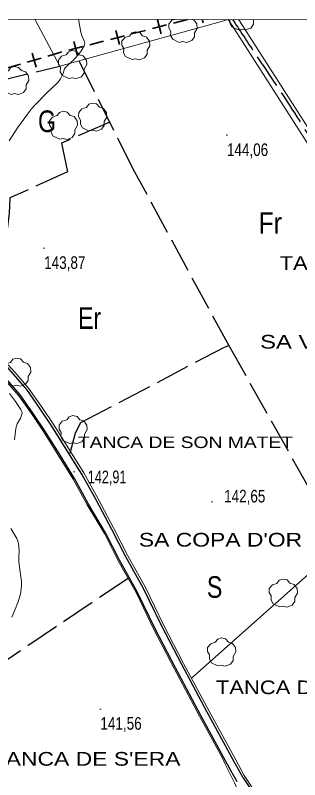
# Model space of a CAD drawing. Extents: x -807245 to 6129983, y -54972206 to 262146364.
# Drawn here: x 488544 to 488741, y 4383600 to 4384130 of the extents above; entities that cross this region are included whole.
import ezdxf
from ezdxf.enums import TextEntityAlignment as Align

# ---------------------------------------------------------------- set-up
doc = ezdxf.new("R2010")
doc.units = 0
doc.header["$LTSCALE"] = 4
doc.linetypes.add('LONG_DASHED', pattern=[7.5, 6, -1.5])
for name, color, linetype, lineweight in [('1', 7, 'Continuous', 13), ('25', 7, 'LONG_DASHED', 25), ('27', 7, 'Continuous', 25), ('29', 7, 'Continuous', 13), ('34', 7, 'Continuous', 35), ('36', 7, 'Continuous', 25), ('38', 7, 'Continuous', 25), ('51', 7, 'Continuous', 13), ('7', 7, 'Continuous', 13), ('9', 7, 'Continuous', 13)]:
    doc.layers.add(name, color=color, linetype=linetype, lineweight=lineweight)
doc.layers.add('31', color=7, linetype='Continuous')
doc.layers.add('5', color=7, linetype='Continuous')

msp = doc.modelspace()

# ---------------------------------------------------------------- linework, layer by layer
at = {"layer": '1'}
msp.add_lwpolyline([(487678, 4384129), (491255.4, 4384123.8), (491252.6, 4381811.5), (487674.1, 4381816.7)], close=True, dxfattribs=at)
at = {"layer": '25'}
for points in [[(488372.88, 4384127.06), (488373.97, 4384123.12), (488396.06, 4384079.88), (488412.22, 4384055.84), (488574.56, 4384095.18)], [(488692.19, 4383900.49), (488625.51, 4384023.7), (488587.87, 4384098.85)], [(488609.18, 4384056.33), (488575.68, 4384041.67), (488579.8, 4384021.67), (488539.84, 4384003.67), (488539.27, 4383993.1), (488537.77, 4383979.91), (488536.19, 4383973.03), (488532.76, 4383968.71), (488528.9, 4383965.38), (488486.3, 4383945.97)], [(488581.61, 4383826.5), (488585.47, 4383840.65), (488589.08, 4383847.74), (488688.78, 4383900.02), (488691.79, 4383901.19), (488769.37, 4383763.08)], [(488621.9, 4383739.52), (488493.76, 4383653.17), (488510.87, 4383620.49), (488455.31, 4383582.13)]]:
    msp.add_lwpolyline(points, dxfattribs=at)
at = {"layer": '27'}
msp.add_spline([(491255.21, 4383970.03), (491244.34, 4383967.52), (491230.36, 4383957.66), (491230.81, 4383957.81), (491230.81, 4383957.81), (491220.15, 4383951.47), (491212.7, 4383943.01), (491205.06, 4383944.23), (491184.85, 4383957.71), (491152.82, 4383981.27), (491128.36, 4384004.58), (491128.29, 4384004.88), (491122.26, 4384021.39), (491095.75, 4384034.59), (491071.07, 4384059.32), (491064.71, 4384065.12)], degree=3, dxfattribs=at)
at = {"layer": '29'}
for p, q in [((488666.31, 4384127.56), (488666.32, 4384127.56)), ((488666.32, 4384127.56), (488666.33, 4384127.56)), ((488666.33, 4384127.56), (488666.34, 4384127.56)), ((488666.34, 4384127.56), (488666.35, 4384127.56)), ((488666.35, 4384127.56), (488666.36, 4384127.56)), ((488666.36, 4384127.56), (488666.37, 4384127.56)), ((488666.37, 4384127.56), (488666.38, 4384127.56)), ((488666.38, 4384127.56), (488666.39, 4384127.56)), ((488666.39, 4384127.56), (488666.4, 4384127.56)), ((488666.4, 4384127.56), (488666.41, 4384127.56)), ((488666.41, 4384127.56), (488666.42, 4384127.56)), ((488666.42, 4384127.56), (488666.43, 4384127.56)), ((488666.43, 4384127.56), (488666.44, 4384127.56)), ((488666.44, 4384127.56), (488666.45, 4384127.56)), ((488666.45, 4384127.56), (488666.46, 4384127.56)), ((488666.46, 4384127.56), (488666.47, 4384127.56)), ((488666.47, 4384127.56), (488666.48, 4384127.56)), ((488666.48, 4384127.56), (488666.49, 4384127.56)), ((488666.49, 4384127.56), (488666.5, 4384127.56)), ((488666.5, 4384127.56), (488666.51, 4384127.56)), ((488666.51, 4384127.56), (488666.52, 4384127.56)), ((488666.52, 4384127.56), (488666.53, 4384127.56)), ((488666.53, 4384127.56), (488666.54, 4384127.56)), ((488666.54, 4384127.56), (488666.55, 4384127.56)), ((488666.55, 4384127.56), (488666.56, 4384127.56)), ((488666.56, 4384127.56), (488666.57, 4384127.56)), ((488666.57, 4384127.56), (488666.58, 4384127.56)), ((488666.58, 4384127.56), (488666.59, 4384127.56)), ((488666.59, 4384127.56), (488666.6, 4384127.56)), ((488666.6, 4384127.56), (488666.61, 4384127.56)), ((488692.49, 4384126.59), (488692.52, 4384127.53))]:
    msp.add_line(p, q, dxfattribs=at)
for points in [[(488657.4, 4384111.65), (488652.86, 4384113.77), (488651.45, 4384116.31), (488651.55, 4384119.29), (488650.18, 4384121.7), (488650.22, 4384124.45), (488652.05, 4384126.65)], [(488652.05, 4384126.65), (488652.38, 4384127.05), (488654.07, 4384127.58)], [(488667.93, 4384126.63), (488669.54, 4384124.48), (488669.78, 4384121.35), (488667.9, 4384118.2), (488667.9, 4384115.52), (488666.08, 4384112.91), (488662.46, 4384111.57), (488659.69, 4384112.2), (488657.4, 4384111.65)], [(488666.61, 4384127.56), (488667.41, 4384127.33), (488667.93, 4384126.63)], [(488698.39, 4384120.33), (488693.85, 4384122.45), (488692.44, 4384124.99), (488692.49, 4384126.59)], [(488708.89, 4384126.57), (488708.89, 4384124.2), (488707.07, 4384121.59), (488703.45, 4384120.25), (488700.68, 4384120.88), (488698.39, 4384120.33)], [(488709.26, 4384127.5), (488708.89, 4384126.88), (488708.89, 4384126.57)]]:
    msp.add_lwpolyline(points, dxfattribs=at)
for points in [[(488624.71, 4384099.64), (488620.17, 4384101.76), (488618.76, 4384104.3), (488618.86, 4384107.28), (488617.49, 4384109.69), (488617.53, 4384112.44), (488619.69, 4384115.04), (488622.88, 4384116.04), (488624.53, 4384118.23), (488627.1, 4384119.06), (488629.96, 4384118.41), (488631.91, 4384116.14), (488634.72, 4384115.32), (488636.85, 4384112.47), (488637.09, 4384109.34), (488635.21, 4384106.19), (488635.21, 4384103.51), (488633.39, 4384100.9), (488629.77, 4384099.56), (488627, 4384100.19)], [(488580.82, 4384086.56), (488576.28, 4384088.68), (488574.87, 4384091.22), (488574.97, 4384094.2), (488573.6, 4384096.61), (488573.64, 4384099.36), (488575.8, 4384101.96), (488578.99, 4384102.96), (488580.64, 4384105.15), (488583.21, 4384105.98), (488586.07, 4384105.33), (488588.02, 4384103.06), (488590.83, 4384102.24), (488592.96, 4384099.39), (488593.2, 4384096.26), (488591.32, 4384093.11), (488591.32, 4384090.43), (488589.5, 4384087.82), (488585.88, 4384086.48), (488583.11, 4384087.11)], [(488540.71, 4384075.54), (488536.17, 4384077.66), (488534.76, 4384080.2), (488534.86, 4384083.18), (488533.49, 4384085.59), (488533.53, 4384088.34), (488535.69, 4384090.94), (488538.88, 4384091.94), (488540.53, 4384094.13), (488543.1, 4384094.96), (488545.96, 4384094.31), (488547.91, 4384092.04), (488550.72, 4384091.22), (488552.85, 4384088.37), (488553.09, 4384085.24), (488551.21, 4384082.09), (488551.21, 4384079.41), (488549.39, 4384076.8), (488545.77, 4384075.46), (488543, 4384076.09)], [(488594.81, 4384050.09), (488590.27, 4384052.21), (488588.86, 4384054.75), (488588.96, 4384057.73), (488587.59, 4384060.14), (488587.63, 4384062.89), (488589.79, 4384065.49), (488592.98, 4384066.49), (488594.63, 4384068.68), (488597.2, 4384069.51), (488600.06, 4384068.86), (488602.01, 4384066.59), (488604.82, 4384065.77), (488606.95, 4384062.92), (488607.19, 4384059.79), (488605.31, 4384056.64), (488605.31, 4384053.96), (488603.49, 4384051.35), (488599.87, 4384050.01), (488597.1, 4384050.64)], [(488574.49, 4384044.39), (488569.95, 4384046.51), (488568.54, 4384049.05), (488568.64, 4384052.03), (488567.27, 4384054.44), (488567.31, 4384057.19), (488569.47, 4384059.79), (488572.66, 4384060.79), (488574.31, 4384062.98), (488576.88, 4384063.81), (488579.74, 4384063.16), (488581.69, 4384060.89), (488584.5, 4384060.07), (488586.63, 4384057.22), (488586.87, 4384054.09), (488584.99, 4384050.94), (488584.99, 4384048.26), (488583.17, 4384045.65), (488579.55, 4384044.31), (488576.78, 4384044.94)], [(488542.08, 4383873.04), (488537.54, 4383875.16), (488536.13, 4383877.7), (488536.23, 4383880.68), (488534.86, 4383883.09), (488534.9, 4383885.84), (488537.06, 4383888.44), (488540.25, 4383889.44), (488541.9, 4383891.63), (488544.47, 4383892.46), (488547.33, 4383891.81), (488549.28, 4383889.54), (488552.09, 4383888.72), (488554.22, 4383885.87), (488554.46, 4383882.74), (488552.58, 4383879.59), (488552.58, 4383876.91), (488550.76, 4383874.3), (488547.14, 4383872.96), (488544.37, 4383873.59)], [(488581.24, 4383833.13), (488576.7, 4383835.25), (488575.29, 4383837.79), (488575.39, 4383840.77), (488574.02, 4383843.18), (488574.06, 4383845.93), (488576.22, 4383848.53), (488579.41, 4383849.53), (488581.06, 4383851.72), (488583.63, 4383852.55), (488586.49, 4383851.9), (488588.44, 4383849.63), (488591.25, 4383848.81), (488593.38, 4383845.96), (488593.62, 4383842.83), (488591.74, 4383839.68), (488591.74, 4383837), (488589.92, 4383834.39), (488586.3, 4383833.05), (488583.53, 4383833.68)], [(488727.06, 4383719.62), (488722.52, 4383721.74), (488721.11, 4383724.28), (488721.21, 4383727.26), (488719.84, 4383729.67), (488719.88, 4383732.42), (488722.04, 4383735.02), (488725.23, 4383736.02), (488726.88, 4383738.21), (488729.45, 4383739.04), (488732.31, 4383738.39), (488734.26, 4383736.12), (488737.07, 4383735.3), (488739.2, 4383732.45), (488739.44, 4383729.32), (488737.56, 4383726.17), (488737.56, 4383723.49), (488735.74, 4383720.88), (488732.12, 4383719.54), (488729.35, 4383720.17)], [(488684.29, 4383678.69), (488679.75, 4383680.81), (488678.34, 4383683.35), (488678.44, 4383686.33), (488677.07, 4383688.74), (488677.11, 4383691.49), (488679.27, 4383694.09), (488682.46, 4383695.09), (488684.11, 4383697.28), (488686.68, 4383698.11), (488689.54, 4383697.46), (488691.49, 4383695.19), (488694.3, 4383694.37), (488696.43, 4383691.52), (488696.67, 4383688.39), (488694.79, 4383685.24), (488694.79, 4383682.56), (488692.97, 4383679.95), (488689.35, 4383678.61), (488686.58, 4383679.24)]]:
    msp.add_lwpolyline(points, close=True, dxfattribs=at)
at = {"layer": '34'}
for p, q in [((488648.52, 4384123.73), (488638.83, 4384121.23)), ((488642.42, 4384127.32), (488644.92, 4384117.64)), ((488663.04, 4384127.48), (488653.36, 4384124.98)), ((488673.35, 4384127.55), (488673.97, 4384125.14)), ((488613.38, 4384119.82), (488615.88, 4384110.13)), ((488633.99, 4384119.98), (488624.31, 4384117.48)), ((488584.33, 4384112.32), (488586.83, 4384102.63)), ((488604.94, 4384112.48), (488595.26, 4384109.97)), ((488619.47, 4384116.23), (488609.79, 4384113.73)), ((488590.42, 4384108.72), (488580.74, 4384106.22)), ((488555.3, 4384104.09), (488558.14, 4384094.5)), ((488575.9, 4384104.97), (488566.31, 4384102.13)), ((488547.13, 4384096.45), (488537.54, 4384093.62)), ((488561.52, 4384100.71), (488551.93, 4384097.87))]:
    msp.add_line(p, q, dxfattribs=at)
at = {"layer": '36'}
for points in [[(488594.48, 4383791.08), (488584.67, 4383808.92), (488572.85, 4383827.97), (488564.11, 4383841.98), (488556.11, 4383853.86), (488546.9, 4383866.95), (488537.66, 4383877.64), (488527.86, 4383890.52)], [(488599.67, 4383793.94), (488589.78, 4383811.91), (488577.88, 4383831.09), (488569.07, 4383845.19), (488560.99, 4383857.21), (488551.56, 4383870.6), (488542.31, 4383881.29), (488538.03, 4383886.26)], [(488701.67, 4383601.03), (488695.34, 4383612.67), (488676.75, 4383646.64), (488659.13, 4383679.6), (488645.12, 4383706.66), (488632.65, 4383732.42), (488620.29, 4383754.47), (488610.66, 4383773.44), (488599.67, 4383793.94)], [(488697.56, 4383598.21), (488690.99, 4383610.29), (488672.39, 4383644.28), (488654.74, 4383677.29), (488640.69, 4383704.44), (488628.25, 4383730.12), (488615.91, 4383752.14), (488606.33, 4383771.02), (488594.48, 4383791.08)], [(488701.67, 4383601.03), (488713.18, 4383583.78), (488720.76, 4383571.83), (488727.27, 4383559.98), (488731.21, 4383549.93), (488737.55, 4383533.06), (488740.6, 4383517.68), (488742.06, 4383501.51), (488745.58, 4383482.85), (488747.68, 4383471.91), (488751.03, 4383460.11), (488755.94, 4383445.19), (488763.36, 4383423.37), (488769.52, 4383401.51), (488775.12, 4383378.28), (488779.4, 4383360.18), (488784.4, 4383341.28), (488787.42, 4383323.42), (488790.51, 4383309.68), (488792.66, 4383293.05), (488794.73, 4383278.89), (488796.8, 4383269.66)]]:
    msp.add_lwpolyline(points, dxfattribs=at)
at = {"layer": '38', "linetype": 'LONG_DASHED'}
msp.add_line((488694.44, 4384127.52), (488695.06, 4384126.59), dxfattribs=at)
msp.add_spline([(488695.06, 4384126.59), (488710.74, 4384102.85), (488739.13, 4384059.92), (488761.9, 4384023.12), (488787.39, 4383981.87), (488812.68, 4383943.17), (488842.39, 4383897.3), (488878.08, 4383842.43), (488896.74, 4383812.06)], degree=3, dxfattribs=at)
at = {"layer": '51'}
for p, q in [((488557.13, 4384127.72), (488557.63, 4384126.79)), ((488688.4, 4384126.6), (488691.48, 4384127.45)), ((488691.43, 4384127.53), (488692.03, 4384126.59)), ((488698.64, 4384127.52), (488699.24, 4384126.58)), ((488763.14, 4383756.78), (488665.94, 4383670.09)), ((488702.48, 4383602.71), (488713.51, 4383586.13))]:
    msp.add_line(p, q, dxfattribs=at)
for points in [[(488557.63, 4384126.79), (488574.56, 4384095.18), (488688.4, 4384126.6)], [(488692.03, 4384126.59), (488771.71, 4384002.16), (488890.28, 4383814.23)], [(488699.24, 4384126.58), (488775.97, 4384006.76), (488894.54, 4383818.83)], [(488593.6, 4383790.6), (488583.8, 4383808.41), (488572, 4383827.43), (488563.27, 4383841.43), (488555.29, 4383853.29), (488546.1, 4383866.33), (488536.94, 4383876.94), (488526.74, 4383890.39)], [(488601.05, 4383794.7), (488591.14, 4383812.71), (488579.22, 4383831.92), (488570.39, 4383846.05), (488562.28, 4383858.1), (488552.8, 4383871.57), (488543.29, 4383882.57), (488538.71, 4383887.69)], [(488702.48, 4383602.71), (488696.67, 4383613.39), (488678.08, 4383647.36), (488660.47, 4383680.3), (488646.47, 4383707.34), (488633.99, 4383733.12), (488621.62, 4383755.18), (488611.98, 4383774.18), (488601.05, 4383794.7)], [(488687.46, 4383614.76), (488671.55, 4383643.83), (488653.9, 4383676.85), (488639.84, 4383704.01), (488627.41, 4383729.68), (488615.07, 4383751.69), (488605.5, 4383770.56), (488593.6, 4383790.6)], [(488687.46, 4383614.76), (488689.38, 4383610.43), (488695.76, 4383597.6), (488703.08, 4383581.39), (488709.12, 4383571.42), (488710.4, 4383565.48), (488711.05, 4383563.44), (488711.41, 4383561.94), (488712.21, 4383559.08), (488712.29, 4383553.45)]]:
    msp.add_lwpolyline(points, dxfattribs=at)
at = {"layer": '7'}
for p, q in [((488690.02, 4384047.12), (488691.02, 4384047.12)), ((488563.17, 4383968.74), (488564.17, 4383968.74)), ((488583.91, 4383813.43), (488584.91, 4383813.43)), ((488679.55, 4383792.54), (488680.55, 4383792.54)), ((488602.22, 4383648.78), (488603.22, 4383648.78))]:
    msp.add_line(p, q, dxfattribs=at)
at = {"layer": '9'}
msp.add_line((488587.46, 4384127.68), (488587.61, 4384126.75), dxfattribs=at)
for points in [[(488587.61, 4384126.75), (488587.67, 4384126.35), (488589.13, 4384118.64), (488589.53, 4384117.05), (488589.94, 4384115.7), (488591.41, 4384112.76), (488591.94, 4384110.75), (488591.76, 4384109.98), (488591.43, 4384109.13), (488589.02, 4384105.26), (488585.73, 4384101.2), (488584.83, 4384100.21), (488583.95, 4384099.29), (488580.8, 4384096.45), (488578.31, 4384093.97), (488577.84, 4384093.28), (488577.45, 4384092.57), (488576.82, 4384089.98), (488575.08, 4384086.32), (488574, 4384084.95), (488572.65, 4384083.42), (488565.6, 4384076.58), (488557.15, 4384068.07), (488554.91, 4384065.49), (488552.72, 4384062.8), (488545.18, 4384052.27), (488539.36, 4384043.18)], [(488539.51, 4383867.8), (488543.82, 4383862.39), (488547.58, 4383856.7), (488548.07, 4383855.39), (488548.31, 4383854.18), (488547.18, 4383850.79), (488544.91, 4383846.86), (488544.43, 4383845.32), (488544.02, 4383843.58), (488543.08, 4383835.67)], [(488540.58, 4383774.03), (488544.7, 4383767.13), (488545.42, 4383765.43), (488545.96, 4383763.82), (488546.37, 4383758.79), (488546, 4383753.84), (488546.04, 4383752.28), (488546.14, 4383750.64), (488547.04, 4383744.05), (488547.85, 4383737.37), (488547.9, 4383735.68), (488547.88, 4383734.05), (488547.16, 4383728.71), (488545.53, 4383723.23), (488544.92, 4383721.52), (488544.25, 4383719.72), (488541.27, 4383712.49)]]:
    msp.add_lwpolyline(points, dxfattribs=at)

# ---------------------------------------------------------------- texts
at = {"layer": '31'}
for s, width, p in [('G', 0.8, (488565.63, 4384049.39)), ('Fr', 0.85, (488720.64, 4383978.75)), ('Er', 0.8, (488595.22, 4383912.72)), ('S', 0.8, (488681.97, 4383726))]:
    msp.add_text(s, height=15, dxfattribs=dict(at, width=width)).set_placement(p, align=Align.CENTER)
at = {"layer": '5'}
for s, height, width, p in [('TANCA', 9.5, 1.2, (488778.79, 4383953.69)), (' SA VINYA', 9.5, 1.3, (488789.72, 4383899.03)), ('TANCA DE SON MATET', 8, 1.25, (488736.41, 4383829.99)), ("SA COPA D'OR", 9.5, 1.25, (488742.71, 4383761.57)), ('TANCA DE FERRO', 9.5, 1.2, (488817.53, 4383659.1)), ("TANCA DE S'ERA", 9.5, 1.25, (488658.26, 4383609.44))]:
    msp.add_text(s, height=height, dxfattribs=dict(at, width=width)).set_placement(p, align=Align.RIGHT)
at = {"layer": '7'}
for s, width, p in [('144,06', 0.8, (488690.52, 4384032.75)), ('143,87', 0.8, (488563.67, 4383954.37)), ('142,91', 0.75, (488593.93, 4383805.57)), ('142,65', 0.8, (488688.56, 4383792.2)), ('141,56', 0.8, (488602.72, 4383634.41))]:
    msp.add_text(s, height=8.75, dxfattribs=dict(at, width=width)).set_placement(p)

doc.saveas('drawing.dxf')
